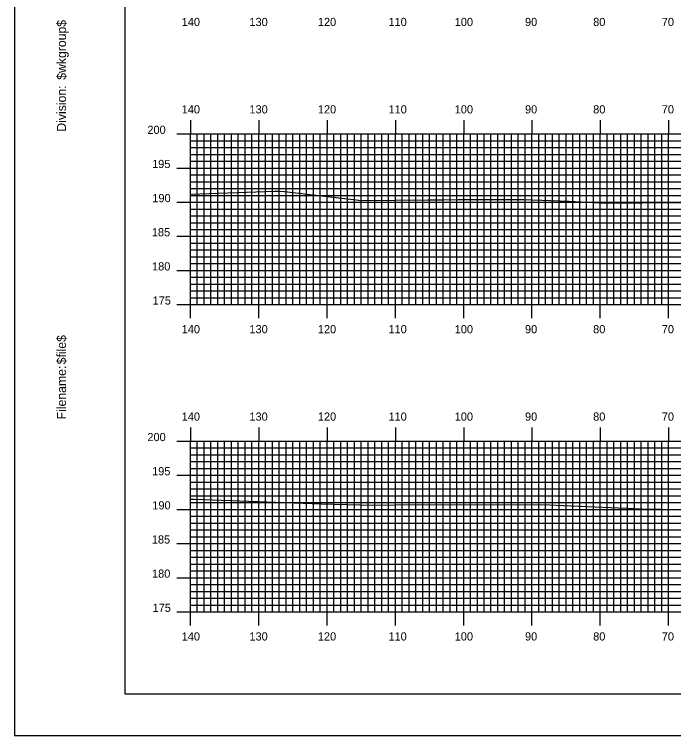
# Model space of a CAD drawing. Extents: x 1797601 to 1797944, y 442591 to 442811.
# Drawn here: x 1797600.7 to 1797697.2, y 442590.5 to 442696.2 of the extents above; entities that cross this region are included whole.
import ezdxf

# ---------------------------------------------------------------- set-up
doc = ezdxf.new("R2010")
doc.units = 0
for name, color, linetype in [('BORDER', 7, 'Continuous'), ('H_V ANNOTATION', 7, 'Continuous'), ('MAJOR', 7, 'Continuous'), ('MINOR', 7, 'Continuous'), ('PLOT BOUNDARY', 7, 'Continuous'), ('S_Roadway_Centerline', 7, 'Continuous')]:
    doc.layers.add(name, color=color, linetype=linetype)

msp = doc.modelspace()

# ---------------------------------------------------------------- linework, layer by layer
at = {"layer": 'BORDER'}
msp.add_lwpolyline([(1797616.84, 442596.67), (1797936.84, 442596.67), (1797936.84, 442806.67), (1797616.84, 442806.67)], close=True, dxfattribs=at)
at = {"layer": 'MAJOR'}
for p, q in [((1797626.44, 442680.67), (1797626.44, 442678.67)), ((1797636.44, 442680.67), (1797636.44, 442678.67)), ((1797646.44, 442680.67), (1797646.44, 442678.67)), ((1797656.44, 442680.67), (1797656.44, 442678.67)), ((1797666.44, 442680.67), (1797666.44, 442678.67)), ((1797676.44, 442680.67), (1797676.44, 442678.67)), ((1797686.44, 442680.67), (1797686.44, 442678.67)), ((1797696.44, 442680.67), (1797696.44, 442678.67)), ((1797624.44, 442678.67), (1797626.44, 442678.67)), ((1797626.44, 442678.67), (1797906.44, 442678.67)), ((1797626.44, 442653.67), (1797626.44, 442678.67)), ((1797626.44, 442653.67), (1797626.44, 442678.67)), ((1797626.44, 442678.67), (1797906.44, 442678.67)), ((1797636.44, 442653.67), (1797636.44, 442678.67)), ((1797646.44, 442653.67), (1797646.44, 442678.67)), ((1797656.44, 442653.67), (1797656.44, 442678.67)), ((1797666.44, 442653.67), (1797666.44, 442678.67)), ((1797676.44, 442653.67), (1797676.44, 442678.67)), ((1797686.44, 442653.67), (1797686.44, 442678.67)), ((1797696.44, 442653.67), (1797696.44, 442678.67)), ((1797624.44, 442673.67), (1797626.44, 442673.67)), ((1797626.44, 442673.67), (1797906.44, 442673.67)), ((1797624.44, 442668.67), (1797626.44, 442668.67)), ((1797626.44, 442668.67), (1797906.44, 442668.67)), ((1797624.44, 442663.67), (1797626.44, 442663.67)), ((1797626.44, 442663.67), (1797906.44, 442663.67)), ((1797624.44, 442658.67), (1797626.44, 442658.67)), ((1797626.44, 442658.67), (1797906.44, 442658.67)), ((1797624.44, 442653.67), (1797626.44, 442653.67)), ((1797626.44, 442653.67), (1797906.44, 442653.67)), ((1797626.44, 442653.67), (1797906.44, 442653.67)), ((1797626.44, 442651.66), (1797626.44, 442653.67)), ((1797636.44, 442651.66), (1797636.44, 442653.67)), ((1797646.44, 442651.66), (1797646.44, 442653.67)), ((1797656.44, 442651.66), (1797656.44, 442653.67)), ((1797666.44, 442651.66), (1797666.44, 442653.67)), ((1797676.44, 442651.66), (1797676.44, 442653.67)), ((1797686.44, 442651.66), (1797686.44, 442653.67)), ((1797696.44, 442651.66), (1797696.44, 442653.67)), ((1797626.44, 442635.67), (1797626.44, 442633.67)), ((1797636.44, 442635.67), (1797636.44, 442633.67)), ((1797646.44, 442635.67), (1797646.44, 442633.67)), ((1797656.44, 442635.67), (1797656.44, 442633.67)), ((1797666.44, 442635.67), (1797666.44, 442633.67)), ((1797676.44, 442635.67), (1797676.44, 442633.67)), ((1797686.44, 442635.67), (1797686.44, 442633.67)), ((1797696.44, 442635.67), (1797696.44, 442633.67)), ((1797624.44, 442633.67), (1797626.44, 442633.67)), ((1797626.44, 442633.67), (1797906.44, 442633.67)), ((1797626.44, 442608.67), (1797626.44, 442633.67)), ((1797626.44, 442608.67), (1797626.44, 442633.67)), ((1797626.44, 442633.67), (1797906.44, 442633.67)), ((1797636.44, 442608.67), (1797636.44, 442633.67)), ((1797646.44, 442608.67), (1797646.44, 442633.67)), ((1797656.44, 442608.67), (1797656.44, 442633.67)), ((1797666.44, 442608.67), (1797666.44, 442633.67)), ((1797676.44, 442608.67), (1797676.44, 442633.67)), ((1797686.44, 442608.67), (1797686.44, 442633.67)), ((1797696.44, 442608.67), (1797696.44, 442633.67)), ((1797624.44, 442628.67), (1797626.44, 442628.67)), ((1797626.44, 442628.67), (1797906.44, 442628.67)), ((1797624.44, 442623.67), (1797626.44, 442623.67)), ((1797626.44, 442623.67), (1797906.44, 442623.67)), ((1797624.44, 442618.67), (1797626.44, 442618.67)), ((1797626.44, 442618.67), (1797906.44, 442618.67)), ((1797624.44, 442613.67), (1797626.44, 442613.67)), ((1797626.44, 442613.67), (1797906.44, 442613.67)), ((1797624.44, 442608.67), (1797626.44, 442608.67)), ((1797626.44, 442608.67), (1797906.44, 442608.67)), ((1797626.44, 442608.67), (1797906.44, 442608.67)), ((1797626.44, 442606.66), (1797626.44, 442608.67)), ((1797636.44, 442606.66), (1797636.44, 442608.67)), ((1797646.44, 442606.66), (1797646.44, 442608.67)), ((1797656.44, 442606.66), (1797656.44, 442608.67)), ((1797666.44, 442606.66), (1797666.44, 442608.67)), ((1797676.44, 442606.66), (1797676.44, 442608.67)), ((1797686.44, 442606.66), (1797686.44, 442608.67)), ((1797696.44, 442606.66), (1797696.44, 442608.67))]:
    msp.add_line(p, q, dxfattribs=at)
at = {"layer": 'MINOR'}
for p, q in [((1797627.44, 442653.67), (1797627.44, 442678.67)), ((1797628.44, 442653.67), (1797628.44, 442678.67)), ((1797629.44, 442653.67), (1797629.44, 442678.67)), ((1797630.44, 442653.67), (1797630.44, 442678.67)), ((1797631.44, 442653.67), (1797631.44, 442678.67)), ((1797632.44, 442653.67), (1797632.44, 442678.67)), ((1797633.44, 442653.67), (1797633.44, 442678.67)), ((1797634.44, 442653.67), (1797634.44, 442678.67)), ((1797635.44, 442653.67), (1797635.44, 442678.67)), ((1797637.44, 442653.67), (1797637.44, 442678.67)), ((1797638.44, 442653.67), (1797638.44, 442678.67)), ((1797639.44, 442653.67), (1797639.44, 442678.67)), ((1797640.44, 442653.67), (1797640.44, 442678.67)), ((1797641.44, 442653.67), (1797641.44, 442678.67)), ((1797642.44, 442653.67), (1797642.44, 442678.67)), ((1797643.44, 442653.67), (1797643.44, 442678.67)), ((1797644.44, 442653.67), (1797644.44, 442678.67)), ((1797645.44, 442653.67), (1797645.44, 442678.67)), ((1797647.44, 442653.67), (1797647.44, 442678.67)), ((1797648.44, 442653.67), (1797648.44, 442678.67)), ((1797649.44, 442653.67), (1797649.44, 442678.67)), ((1797650.44, 442653.67), (1797650.44, 442678.67)), ((1797651.44, 442653.67), (1797651.44, 442678.67)), ((1797652.44, 442653.67), (1797652.44, 442678.67)), ((1797653.44, 442653.67), (1797653.44, 442678.67)), ((1797654.44, 442653.67), (1797654.44, 442678.67)), ((1797655.44, 442653.67), (1797655.44, 442678.67)), ((1797657.44, 442653.67), (1797657.44, 442678.67)), ((1797658.44, 442653.67), (1797658.44, 442678.67)), ((1797659.44, 442653.67), (1797659.44, 442678.67)), ((1797660.44, 442653.67), (1797660.44, 442678.67)), ((1797661.44, 442653.67), (1797661.44, 442678.67)), ((1797662.44, 442653.67), (1797662.44, 442678.67)), ((1797663.44, 442653.67), (1797663.44, 442678.67)), ((1797664.44, 442653.67), (1797664.44, 442678.67)), ((1797665.44, 442653.67), (1797665.44, 442678.67)), ((1797667.44, 442653.67), (1797667.44, 442678.67)), ((1797668.44, 442653.67), (1797668.44, 442678.67)), ((1797669.44, 442653.67), (1797669.44, 442678.67)), ((1797670.44, 442653.67), (1797670.44, 442678.67)), ((1797671.44, 442653.67), (1797671.44, 442678.67)), ((1797672.44, 442653.67), (1797672.44, 442678.67)), ((1797673.44, 442653.67), (1797673.44, 442678.67)), ((1797674.44, 442653.67), (1797674.44, 442678.67)), ((1797675.44, 442653.67), (1797675.44, 442678.67)), ((1797677.44, 442653.67), (1797677.44, 442678.67)), ((1797678.44, 442653.67), (1797678.44, 442678.67)), ((1797679.44, 442653.67), (1797679.44, 442678.67)), ((1797680.44, 442653.67), (1797680.44, 442678.67)), ((1797681.44, 442653.67), (1797681.44, 442678.67)), ((1797682.44, 442653.67), (1797682.44, 442678.67)), ((1797683.44, 442653.67), (1797683.44, 442678.67)), ((1797684.44, 442653.67), (1797684.44, 442678.67)), ((1797685.44, 442653.67), (1797685.44, 442678.67)), ((1797687.44, 442653.67), (1797687.44, 442678.67)), ((1797688.44, 442653.67), (1797688.44, 442678.67)), ((1797689.44, 442653.67), (1797689.44, 442678.67)), ((1797690.44, 442653.67), (1797690.44, 442678.67)), ((1797691.44, 442653.67), (1797691.44, 442678.67)), ((1797692.44, 442653.67), (1797692.44, 442678.67)), ((1797693.44, 442653.67), (1797693.44, 442678.67)), ((1797694.44, 442653.67), (1797694.44, 442678.67)), ((1797695.44, 442653.67), (1797695.44, 442678.67)), ((1797626.44, 442677.67), (1797906.44, 442677.67)), ((1797626.44, 442677.67), (1797628.45, 442677.67)), ((1797626.44, 442676.67), (1797906.44, 442676.67)), ((1797626.44, 442676.67), (1797628.45, 442676.67)), ((1797626.44, 442675.67), (1797906.44, 442675.67)), ((1797626.44, 442675.67), (1797628.45, 442675.67)), ((1797626.44, 442674.67), (1797906.44, 442674.67)), ((1797626.44, 442674.67), (1797628.45, 442674.67)), ((1797626.44, 442672.67), (1797906.44, 442672.67)), ((1797626.44, 442672.67), (1797628.45, 442672.67)), ((1797626.44, 442671.67), (1797906.44, 442671.67)), ((1797626.44, 442671.67), (1797628.45, 442671.67)), ((1797626.44, 442670.67), (1797906.44, 442670.67)), ((1797626.44, 442670.67), (1797628.45, 442670.67)), ((1797626.44, 442669.67), (1797906.44, 442669.67)), ((1797626.44, 442669.67), (1797628.45, 442669.67)), ((1797626.44, 442667.67), (1797906.44, 442667.67)), ((1797626.44, 442667.67), (1797628.45, 442667.67)), ((1797626.44, 442666.67), (1797906.44, 442666.67)), ((1797626.44, 442666.67), (1797628.45, 442666.67)), ((1797626.44, 442665.67), (1797906.44, 442665.67)), ((1797626.44, 442665.67), (1797628.45, 442665.67)), ((1797626.44, 442664.67), (1797906.44, 442664.67)), ((1797626.44, 442664.67), (1797628.45, 442664.67)), ((1797626.44, 442662.67), (1797906.44, 442662.67)), ((1797626.44, 442662.67), (1797628.45, 442662.67)), ((1797626.44, 442661.67), (1797906.44, 442661.67)), ((1797626.44, 442661.67), (1797628.45, 442661.67)), ((1797626.44, 442660.67), (1797906.44, 442660.67)), ((1797626.44, 442660.67), (1797628.45, 442660.67)), ((1797626.44, 442659.67), (1797906.44, 442659.67)), ((1797626.44, 442659.67), (1797628.45, 442659.67)), ((1797626.44, 442657.67), (1797906.44, 442657.67)), ((1797626.44, 442657.67), (1797628.45, 442657.67)), ((1797626.44, 442656.67), (1797906.44, 442656.67)), ((1797626.44, 442656.67), (1797628.45, 442656.67)), ((1797626.44, 442655.67), (1797906.44, 442655.67)), ((1797626.44, 442655.67), (1797628.45, 442655.67)), ((1797626.44, 442654.67), (1797906.44, 442654.67)), ((1797626.44, 442654.67), (1797628.45, 442654.67)), ((1797627.44, 442608.67), (1797627.44, 442633.67)), ((1797628.44, 442608.67), (1797628.44, 442633.67)), ((1797629.44, 442608.67), (1797629.44, 442633.67)), ((1797630.44, 442608.67), (1797630.44, 442633.67)), ((1797631.44, 442608.67), (1797631.44, 442633.67)), ((1797632.44, 442608.67), (1797632.44, 442633.67)), ((1797633.44, 442608.67), (1797633.44, 442633.67)), ((1797634.44, 442608.67), (1797634.44, 442633.67)), ((1797635.44, 442608.67), (1797635.44, 442633.67)), ((1797637.44, 442608.67), (1797637.44, 442633.67)), ((1797638.44, 442608.67), (1797638.44, 442633.67)), ((1797639.44, 442608.67), (1797639.44, 442633.67)), ((1797640.44, 442608.67), (1797640.44, 442633.67)), ((1797641.44, 442608.67), (1797641.44, 442633.67)), ((1797642.44, 442608.67), (1797642.44, 442633.67)), ((1797643.44, 442608.67), (1797643.44, 442633.67)), ((1797644.44, 442608.67), (1797644.44, 442633.67)), ((1797645.44, 442608.67), (1797645.44, 442633.67)), ((1797647.44, 442608.67), (1797647.44, 442633.67)), ((1797648.44, 442608.67), (1797648.44, 442633.67)), ((1797649.44, 442608.67), (1797649.44, 442633.67)), ((1797650.44, 442608.67), (1797650.44, 442633.67)), ((1797651.44, 442608.67), (1797651.44, 442633.67)), ((1797652.44, 442608.67), (1797652.44, 442633.67)), ((1797653.44, 442608.67), (1797653.44, 442633.67)), ((1797654.44, 442608.67), (1797654.44, 442633.67)), ((1797655.44, 442608.67), (1797655.44, 442633.67)), ((1797657.44, 442608.67), (1797657.44, 442633.67)), ((1797658.44, 442608.67), (1797658.44, 442633.67)), ((1797659.44, 442608.67), (1797659.44, 442633.67)), ((1797660.44, 442608.67), (1797660.44, 442633.67)), ((1797661.44, 442608.67), (1797661.44, 442633.67)), ((1797662.44, 442608.67), (1797662.44, 442633.67)), ((1797663.44, 442608.67), (1797663.44, 442633.67)), ((1797664.44, 442608.67), (1797664.44, 442633.67)), ((1797665.44, 442608.67), (1797665.44, 442633.67)), ((1797667.44, 442608.67), (1797667.44, 442633.67)), ((1797668.44, 442608.67), (1797668.44, 442633.67)), ((1797669.44, 442608.67), (1797669.44, 442633.67)), ((1797670.44, 442608.67), (1797670.44, 442633.67)), ((1797671.44, 442608.67), (1797671.44, 442633.67)), ((1797672.44, 442608.67), (1797672.44, 442633.67)), ((1797673.44, 442608.67), (1797673.44, 442633.67)), ((1797674.44, 442608.67), (1797674.44, 442633.67)), ((1797675.44, 442608.67), (1797675.44, 442633.67)), ((1797677.44, 442608.67), (1797677.44, 442633.67)), ((1797678.44, 442608.67), (1797678.44, 442633.67)), ((1797679.44, 442608.67), (1797679.44, 442633.67)), ((1797680.44, 442608.67), (1797680.44, 442633.67)), ((1797681.44, 442608.67), (1797681.44, 442633.67)), ((1797682.44, 442608.67), (1797682.44, 442633.67)), ((1797683.44, 442608.67), (1797683.44, 442633.67)), ((1797684.44, 442608.67), (1797684.44, 442633.67)), ((1797685.44, 442608.67), (1797685.44, 442633.67)), ((1797687.44, 442608.67), (1797687.44, 442633.67)), ((1797688.44, 442608.67), (1797688.44, 442633.67)), ((1797689.44, 442608.67), (1797689.44, 442633.67)), ((1797690.44, 442608.67), (1797690.44, 442633.67)), ((1797691.44, 442608.67), (1797691.44, 442633.67)), ((1797692.44, 442608.67), (1797692.44, 442633.67)), ((1797693.44, 442608.67), (1797693.44, 442633.67)), ((1797694.44, 442608.67), (1797694.44, 442633.67)), ((1797695.44, 442608.67), (1797695.44, 442633.67)), ((1797626.44, 442632.67), (1797906.44, 442632.67)), ((1797626.44, 442632.67), (1797628.45, 442632.67)), ((1797626.44, 442631.67), (1797906.44, 442631.67)), ((1797626.44, 442631.67), (1797628.45, 442631.67)), ((1797626.44, 442630.67), (1797906.44, 442630.67)), ((1797626.44, 442630.67), (1797628.45, 442630.67)), ((1797626.44, 442629.67), (1797906.44, 442629.67)), ((1797626.44, 442629.67), (1797628.45, 442629.67)), ((1797626.44, 442627.67), (1797906.44, 442627.67)), ((1797626.44, 442627.67), (1797628.45, 442627.67)), ((1797626.44, 442626.67), (1797906.44, 442626.67)), ((1797626.44, 442626.67), (1797628.45, 442626.67)), ((1797626.44, 442625.67), (1797906.44, 442625.67)), ((1797626.44, 442625.67), (1797628.45, 442625.67)), ((1797626.44, 442624.67), (1797906.44, 442624.67)), ((1797626.44, 442624.67), (1797628.45, 442624.67)), ((1797626.44, 442622.67), (1797906.44, 442622.67)), ((1797626.44, 442622.67), (1797628.45, 442622.67)), ((1797626.44, 442621.67), (1797906.44, 442621.67)), ((1797626.44, 442621.67), (1797628.45, 442621.67)), ((1797626.44, 442620.67), (1797906.44, 442620.67)), ((1797626.44, 442620.67), (1797628.45, 442620.67)), ((1797626.44, 442619.67), (1797906.44, 442619.67)), ((1797626.44, 442619.67), (1797628.45, 442619.67)), ((1797626.44, 442617.67), (1797906.44, 442617.67)), ((1797626.44, 442617.67), (1797628.45, 442617.67)), ((1797626.44, 442616.67), (1797906.44, 442616.67)), ((1797626.44, 442616.67), (1797628.45, 442616.67)), ((1797626.44, 442615.67), (1797906.44, 442615.67)), ((1797626.44, 442615.67), (1797628.45, 442615.67)), ((1797626.44, 442614.67), (1797906.44, 442614.67)), ((1797626.44, 442614.67), (1797628.45, 442614.67)), ((1797626.44, 442612.67), (1797906.44, 442612.67)), ((1797626.44, 442612.67), (1797628.45, 442612.67)), ((1797626.44, 442611.67), (1797906.44, 442611.67)), ((1797626.44, 442611.67), (1797628.45, 442611.67)), ((1797626.44, 442610.67), (1797906.44, 442610.67)), ((1797626.44, 442610.67), (1797628.45, 442610.67)), ((1797626.44, 442609.67), (1797906.44, 442609.67)), ((1797626.44, 442609.67), (1797628.45, 442609.67))]:
    msp.add_line(p, q, dxfattribs=at)
at = {"layer": 'PLOT BOUNDARY'}
msp.add_lwpolyline([(1797600.66, 442590.55), (1797940.66, 442590.55), (1797940.66, 442810.55), (1797600.66, 442810.55)], close=True, dxfattribs=at)
at = {"layer": 'S_Roadway_Centerline'}
for points in [[(1797626.44, 442669.87), (1797638.73, 442670.27), (1797639.58, 442670.28), (1797640.2, 442670.23), (1797651.53, 442668.94), (1797661.2, 442669.02), (1797663.39, 442669.01), (1797665.68, 442669.05), (1797675.19, 442669.08), (1797681.9, 442668.81), (1797686.26, 442668.6), (1797692.6, 442668.6), (1797703.82, 442668.64)], [(1797626.44, 442625.19), (1797627.01, 442625.18), (1797645.57, 442624.5), (1797653.15, 442624.31), (1797659.86, 442624.38), (1797679.03, 442624.36), (1797681.03, 442624.25), (1797692.59, 442623.76), (1797701.04, 442623.61)]]:
    msp.add_lwpolyline(points, dxfattribs=at)

# ---------------------------------------------------------------- texts
at = {"layer": 'BORDER'}
for s, p in [('$wkgroup$', (1797608.21, 442686.6)), ('Division:', (1797608.21, 442679)), ('$file$', (1797608.21, 442644.92)), ('Filename:', (1797608.21, 442636.86))]:
    msp.add_text(s, height=1.339, rotation=90, dxfattribs=at).set_placement(p)
at = {"layer": 'H_V ANNOTATION'}
for s, p in [('140', (1797625.15, 442694.47)), ('130', (1797635.07, 442694.47)), ('120', (1797645.09, 442694.47)), ('110', (1797655.43, 442694.47)), ('100', (1797665.13, 442694.47)), ('90', (1797675.42, 442694.47)), ('80', (1797685.4, 442694.47)), ('70', (1797695.45, 442694.47)), ('140', (1797625.15, 442681.67)), ('130', (1797635.07, 442681.67)), ('120', (1797645.09, 442681.67)), ('110', (1797655.43, 442681.67)), ('100', (1797665.13, 442681.67)), ('90', (1797675.42, 442681.67)), ('80', (1797685.4, 442681.67)), ('70', (1797695.45, 442681.67)), ('200', (1797620.13, 442678.67)), ('195', (1797620.82, 442673.67)), ('190', (1797620.85, 442668.67)), ('185', (1797620.78, 442663.67)), ('180', (1797620.81, 442658.67)), ('175', (1797620.89, 442653.67)), ('140', (1797625.15, 442649.47)), ('130', (1797635.07, 442649.47)), ('120', (1797645.09, 442649.47)), ('110', (1797655.43, 442649.47)), ('100', (1797665.13, 442649.47)), ('90', (1797675.42, 442649.47)), ('80', (1797685.4, 442649.47)), ('70', (1797695.45, 442649.47)), ('140', (1797625.15, 442636.67)), ('130', (1797635.07, 442636.67)), ('120', (1797645.09, 442636.67)), ('110', (1797655.43, 442636.67)), ('100', (1797665.13, 442636.67)), ('90', (1797675.42, 442636.67)), ('80', (1797685.4, 442636.67)), ('70', (1797695.45, 442636.67)), ('200', (1797620.13, 442633.67)), ('195', (1797620.82, 442628.67)), ('190', (1797620.85, 442623.67)), ('185', (1797620.78, 442618.67)), ('180', (1797620.81, 442613.67)), ('175', (1797620.89, 442608.67)), ('140', (1797625.15, 442604.47)), ('130', (1797635.07, 442604.47)), ('120', (1797645.09, 442604.47)), ('110', (1797655.43, 442604.47)), ('100', (1797665.13, 442604.47)), ('90', (1797675.42, 442604.47)), ('80', (1797685.4, 442604.47)), ('70', (1797695.45, 442604.47))]:
    msp.add_text(s, height=1.2, dxfattribs=at).set_placement(p)
at = {"layer": 'MAJOR'}
for p in [(1797626.44, 442653.67), (1797626.44, 442608.67)]:
    msp.add_text('-', height=0.012, dxfattribs=at).set_placement(p)

doc.saveas('drawing.dxf')
